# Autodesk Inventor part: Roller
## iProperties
Created: 2006-09
Part Number: Roller
Document SubType Name: Modeling
Designer: Maxime Debono
Mass: 1.82212 g
Surface Area: 10.6814 cm^2
Volume: 1.82212 cm^3
Density: 1 g/cm^3
Author: Maxime Debono
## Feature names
1. Extrusion1
2. Extrusion2
3. Mirror1
4. Split1
5. Trennen2
6. Trennen3
